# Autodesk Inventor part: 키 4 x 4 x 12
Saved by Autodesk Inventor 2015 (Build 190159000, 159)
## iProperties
Created: 2025-08
Part Number: 키 4 x 4 x 12
Material: 일반
Document SubType Name: Modeling
Designer: user
Density: 1 g/cm^3
Appearance: 기본값
Author: jhkim
Description: 키 및 해당 키홈
Creation Date: 2025-08-05
Sending System: Autodesk Inventor 2026
Preprocessor: ST-DEVELOPER v20.1
Author: user
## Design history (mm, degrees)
node "키 4 x 4 x 121"
body "Solid1"
node "기준1"
